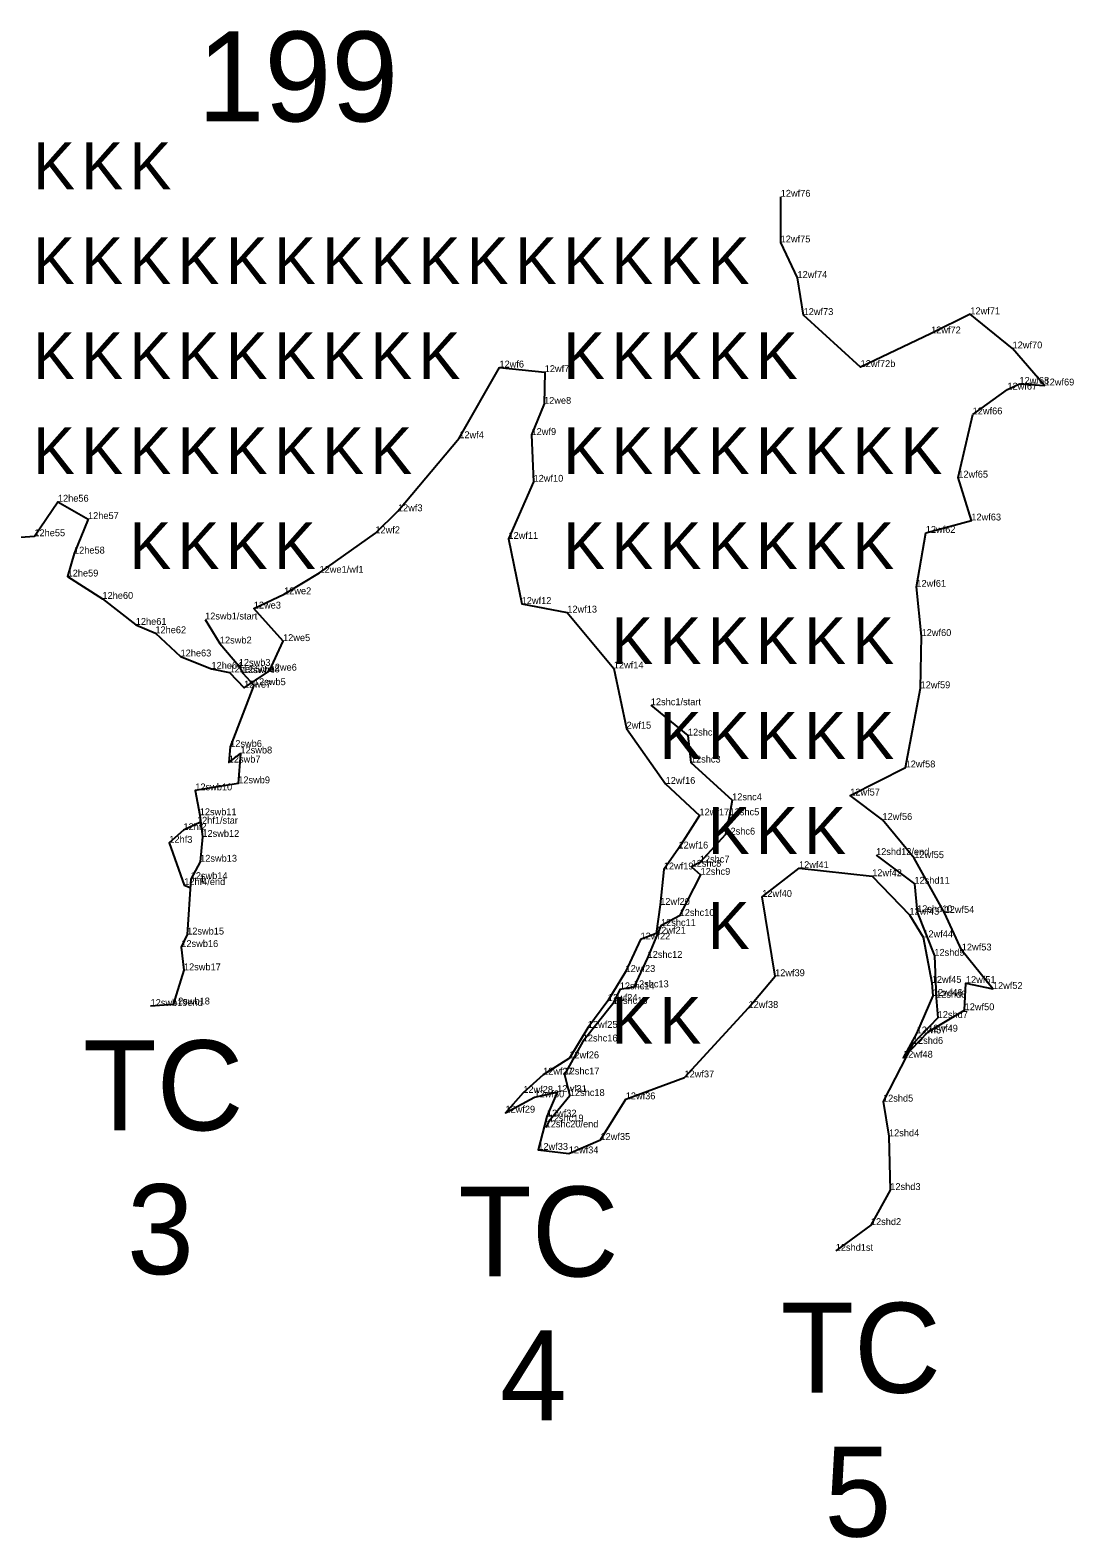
# Model space of a CAD drawing. Extents: x 2072529 to 2268812, y 436423 to 470008.
# Drawn here: x 2237884 to 2238642, y 451648 to 452743 of the extents above; entities that cross this region are included whole.
import ezdxf

# ---------------------------------------------------------------- set-up
doc = ezdxf.new("R2010")
doc.units = 0
for name, color, linetype in [('Old_Level_10', 7, 'Continuous'), ('Old_Level_20', 7, 'Continuous'), ('Old_Level_52', 7, 'Continuous'), ('Old_Level_55', 7, 'Continuous'), ('Old_Level_60', 7, 'Continuous'), ('Old_Level_62', 7, 'Continuous')]:
    doc.layers.add(name, color=color, linetype=linetype)

msp = doc.modelspace()

# ---------------------------------------------------------------- linework, layer by layer
at = {"layer": 'Old_Level_10'}
for points in [[(2238010.694, 452314.93), (2238021.436, 452297.482), (2238035.128, 452281.22), (2238038.188, 452275.967), (2238046.181, 452267.208), (2238028.905, 452222.291), (2238027.87, 452210.961), (2238036.35, 452217.58), (2238034.759, 452195.863), (2238003.583, 452190.757), (2238006.802, 452172.686), (2238008.719, 452156.976), (2238007.099, 452138.905), (2238000.224, 452126.284), (2237997.67, 452086.001), (2237993.422, 452076.932), (2237995.326, 452060.005), (2237987.388, 452035.188), (2237971.089, 452034.064)], [(2238334.377, 452252.615), (2238361.329, 452230.577), (2238363.498, 452210.976), (2238393.449, 452183.574), (2238391.606, 452172.684), (2238388.577, 452158.621), (2238369.952, 452138.34), (2238363.996, 452135.238), (2238370.517, 452129.385), (2238355.316, 452099.515), (2238341.777, 452092.23), (2238332.039, 452069.053), (2238322.096, 452047.692), (2238311.831, 452046.169), (2238306.711, 452035.572), (2238284.949, 452008.295), (2238271.773, 451984.32), (2238275.587, 451968.691), (2238260.246, 451950.175), (2238258.026, 451945.854)], [(2238497.962, 452143.757), (2238525.811, 452122.899), (2238527.782, 452102.252), (2238540.299, 452070.547), (2238541.55, 452040.093), (2238542.723, 452025.354), (2238524.713, 452006.572), (2238503.009, 451964.61), (2238507.357, 451939.378), (2238508.314, 451900.321), (2238494.238, 451874.878), (2238468.676, 451856.183)]]:
    msp.add_lwpolyline(points, dxfattribs=at)
at = {"layer": 'Old_Level_20'}
for p, q in [((2238428.754, 452622.108), (2238428.754, 452622.108)), ((2238428.688, 452588.913), (2238428.688, 452588.913)), ((2238440.919, 452563.086), (2238440.919, 452563.086)), ((2238445.35, 452536.145), (2238445.35, 452536.145)), ((2238566.421, 452536.684), (2238566.421, 452536.684)), ((2238537.913, 452522.786), (2238537.913, 452522.786)), ((2238597.097, 452511.893), (2238597.097, 452511.893)), ((2238224.44, 452498.01), (2238224.44, 452498.01)), ((2238257.347, 452494.702), (2238257.347, 452494.702)), ((2238486.692, 452498.346), (2238486.692, 452498.346)), ((2238593.365, 452481.95), (2238593.365, 452481.95)), ((2238602.128, 452486.166), (2238602.128, 452486.166)), ((2238620.342, 452484.972), (2238620.342, 452484.972)), ((2238256.845, 452471.636), (2238256.845, 452471.636)), ((2238568.126, 452463.954), (2238568.126, 452463.954)), ((2238195.306, 452446.648), (2238195.306, 452446.648)), ((2238247.757, 452448.981), (2238247.757, 452448.981)), ((2238249.24, 452415), (2238249.24, 452415)), ((2238557.699, 452417.986), (2238557.699, 452417.986)), ((2237903.805, 452400.503), (2237903.805, 452400.503)), ((2238150.75, 452393.563), (2238150.75, 452393.563)), ((2237925.67, 452387.897), (2237925.67, 452387.897)), ((2238567.164, 452386.879), (2238567.164, 452386.879)), ((2237886.707, 452375.423), (2237886.707, 452375.423)), ((2238134.357, 452377.566), (2238134.357, 452377.566)), ((2238230.999, 452373.486), (2238230.999, 452373.486)), ((2238534.042, 452377.877), (2238534.042, 452377.877)), ((2237915.502, 452362.798), (2237915.502, 452362.798)), ((2238093.818, 452348.854), (2238093.818, 452348.854)), ((2237910.844, 452346.147), (2237910.844, 452346.147)), ((2238527.222, 452338.653), (2238527.222, 452338.653)), ((2237936.142, 452329.916), (2237936.142, 452329.916)), ((2238068.042, 452333.209), (2238068.042, 452333.209)), ((2238240.609, 452326.185), (2238240.609, 452326.185)), ((2238010.694, 452314.93), (2238010.694, 452314.93)), ((2238046.054, 452322.857), (2238046.054, 452322.857)), ((2238273.736, 452319.926), (2238273.736, 452319.926)), ((2237960.357, 452311.031), (2237960.357, 452311.031)), ((2237974.582, 452304.915), (2237974.582, 452304.915)), ((2238021.436, 452297.482), (2238021.436, 452297.482)), ((2238067.306, 452299.224), (2238067.306, 452299.224)), ((2238531.044, 452302.91), (2238531.044, 452302.91)), ((2237992.865, 452288.065), (2237992.865, 452288.065)), ((2238035.128, 452281.22), (2238035.128, 452281.22)), ((2238015.323, 452279.08), (2238015.323, 452279.08)), ((2238028.454, 452276.468), (2238028.454, 452276.468)), ((2238038.188, 452275.967), (2238038.188, 452275.967)), ((2238057.58, 452277.721), (2238057.58, 452277.721)), ((2238307.495, 452279.357), (2238307.495, 452279.357)), ((2238038.976, 452265.371), (2238038.976, 452265.371)), ((2238046.181, 452267.208), (2238046.181, 452267.208)), ((2238530.302, 452264.957), (2238530.302, 452264.957)), ((2238334.377, 452252.615), (2238334.377, 452252.615)), ((2238316.78, 452235.619), (2238316.78, 452235.619)), ((2238361.329, 452230.577), (2238361.329, 452230.577)), ((2238028.905, 452222.291), (2238028.905, 452222.291)), ((2238036.35, 452217.58), (2238036.35, 452217.58)), ((2238027.87, 452210.961), (2238027.87, 452210.961)), ((2238363.498, 452210.976), (2238363.498, 452210.976)), ((2238519.451, 452207.413), (2238519.451, 452207.413)), ((2238034.759, 452195.863), (2238034.759, 452195.863)), ((2238345.147, 452195.473), (2238345.147, 452195.473)), ((2238003.583, 452190.757), (2238003.583, 452190.757)), ((2238393.449, 452183.574), (2238393.449, 452183.574)), ((2238479.177, 452186.975), (2238479.177, 452186.975)), ((2238006.802, 452172.686), (2238006.802, 452172.686)), ((2238369.696, 452172.554), (2238369.696, 452172.554)), ((2238391.606, 452172.684), (2238391.606, 452172.684)), ((2237994.958, 452161.838), (2237994.958, 452161.838)), ((2238004.774, 452166.517), (2238004.774, 452166.517)), ((2238502.65, 452169.283), (2238502.65, 452169.283)), ((2237984.711, 452152.648), (2237984.711, 452152.648)), ((2238008.719, 452156.976), (2238008.719, 452156.976)), ((2238388.577, 452158.621), (2238388.577, 452158.621)), ((2238007.099, 452138.905), (2238007.099, 452138.905)), ((2238354.479, 452148.509), (2238354.479, 452148.509)), ((2238497.962, 452143.757), (2238497.962, 452143.757)), ((2238525.69, 452141.534), (2238525.69, 452141.534)), ((2238343.8, 452133.304), (2238343.8, 452133.304)), ((2238363.996, 452135.238), (2238363.996, 452135.238)), ((2238369.952, 452138.34), (2238369.952, 452138.34)), ((2238370.517, 452129.385), (2238370.517, 452129.385)), ((2238442.006, 452134.254), (2238442.006, 452134.254)), ((2238495.147, 452128.396), (2238495.147, 452128.396)), ((2237995.555, 452121.937), (2237995.555, 452121.937)), ((2238000.224, 452126.284), (2238000.224, 452126.284)), ((2238525.811, 452122.899), (2238525.811, 452122.899)), ((2238341.19, 452107.554), (2238341.19, 452107.554)), ((2238415.298, 452113.343), (2238415.298, 452113.343)), ((2238355.316, 452099.515), (2238355.316, 452099.515)), ((2238522.222, 452100.399), (2238522.222, 452100.399)), ((2238527.782, 452102.252), (2238527.782, 452102.252)), ((2238547.732, 452101.763), (2238547.732, 452101.763)), ((2237997.67, 452086.001), (2237997.67, 452086.001)), ((2238338.222, 452086.667), (2238338.222, 452086.667)), ((2238341.777, 452092.23), (2238341.777, 452092.23)), ((2237993.422, 452076.932), (2237993.422, 452076.932)), ((2238326.939, 452082.393), (2238326.939, 452082.393)), ((2238532.285, 452083.974), (2238532.285, 452083.974)), ((2238560.242, 452074.441), (2238560.242, 452074.441)), ((2238332.039, 452069.053), (2238332.039, 452069.053)), ((2238540.299, 452070.547), (2238540.299, 452070.547)), ((2237995.326, 452060.005), (2237995.326, 452060.005)), ((2238316.036, 452058.821), (2238316.036, 452058.821)), ((2238424.641, 452055.729), (2238424.641, 452055.729)), ((2238311.831, 452046.169), (2238311.831, 452046.169)), ((2238322.096, 452047.692), (2238322.096, 452047.692)), ((2238538.391, 452050.899), (2238538.391, 452050.899)), ((2238539.198, 452041.453), (2238539.198, 452041.453)), ((2238563.236, 452050.769), (2238563.236, 452050.769)), ((2238582.841, 452046.454), (2238582.841, 452046.454)), ((2237971.089, 452034.064), (2237971.089, 452034.064)), ((2237987.388, 452035.188), (2237987.388, 452035.188)), ((2238303.159, 452037.74), (2238303.159, 452037.74)), ((2238306.711, 452035.572), (2238306.711, 452035.572)), ((2238405.34, 452032.672), (2238405.34, 452032.672)), ((2238541.55, 452040.093), (2238541.55, 452040.093)), ((2238562.293, 452031.009), (2238562.293, 452031.009)), ((2238542.723, 452025.354), (2238542.723, 452025.354)), ((2238284.949, 452008.295), (2238284.949, 452008.295)), ((2238288.648, 452018.187), (2238288.648, 452018.187)), ((2238527.444, 452014.123), (2238527.444, 452014.123)), ((2238535.792, 452015.406), (2238535.792, 452015.406)), ((2238517.576, 451996.474), (2238517.576, 451996.474)), ((2238524.713, 452006.572), (2238524.713, 452006.572)), ((2238275.222, 451996.049), (2238275.222, 451996.049)), ((2238256.128, 451984.144), (2238256.128, 451984.144)), ((2238271.773, 451984.32), (2238271.773, 451984.32)), ((2238358.819, 451982.175), (2238358.819, 451982.175)), ((2238241.784, 451970.96), (2238241.784, 451970.96)), ((2238249.919, 451967.741), (2238249.919, 451967.741)), ((2238266.359, 451971.532), (2238266.359, 451971.532)), ((2238275.587, 451968.691), (2238275.587, 451968.691)), ((2238316.145, 451966.255), (2238316.145, 451966.255)), ((2238503.009, 451964.61), (2238503.009, 451964.61)), ((2238228.787, 451956.554), (2238228.787, 451956.554)), ((2238258.869, 451953.728), (2238258.869, 451953.728)), ((2238258.026, 451945.854), (2238258.026, 451945.854)), ((2238260.246, 451950.175), (2238260.246, 451950.175)), ((2238297.838, 451936.702), (2238297.838, 451936.702)), ((2238507.357, 451939.378), (2238507.357, 451939.378)), ((2238252.683, 451929.538), (2238252.683, 451929.538)), ((2238274.77, 451927.01), (2238274.77, 451927.01)), ((2238508.314, 451900.321), (2238508.314, 451900.321)), ((2238494.238, 451874.878), (2238494.238, 451874.878)), ((2238468.676, 451856.183), (2238468.676, 451856.183))]:
    msp.add_line(p, q, dxfattribs=at)
at = {"layer": 'Old_Level_52'}
for points in [[(2238568.126, 452463.954), (2238593.365, 452481.95), (2238602.128, 452486.166), (2238620.342, 452484.972), (2238597.097, 452511.893), (2238566.421, 452536.684), (2238537.913, 452522.786), (2238486.692, 452498.346), (2238445.35, 452536.145), (2238440.919, 452563.086), (2238428.688, 452588.913), (2238428.754, 452622.108)], [(2237853.078, 452372.986), (2237886.707, 452375.423), (2237903.805, 452400.503), (2237925.67, 452387.897), (2237915.502, 452362.798), (2237910.844, 452346.147), (2237936.142, 452329.916), (2237960.357, 452311.031), (2237974.582, 452304.915), (2237992.865, 452288.065), (2238015.323, 452279.08), (2238028.454, 452276.468), (2238038.976, 452265.371), (2238057.58, 452277.721), (2238067.306, 452299.224), (2238046.054, 452322.857), (2238068.042, 452333.209), (2238093.818, 452348.854), (2238134.357, 452377.566), (2238150.75, 452393.563), (2238195.306, 452446.648), (2238224.44, 452498.01), (2238257.347, 452494.702), (2238256.845, 452471.636), (2238247.757, 452448.981), (2238249.24, 452415), (2238230.999, 452373.486), (2238240.609, 452326.185), (2238273.736, 452319.926), (2238307.495, 452279.357), (2238316.78, 452235.619), (2238345.147, 452195.473), (2238369.696, 452172.554), (2238354.479, 452148.509), (2238343.8, 452133.304), (2238341.19, 452107.554), (2238338.222, 452086.667), (2238326.939, 452082.393), (2238316.036, 452058.821), (2238303.159, 452037.74), (2238288.648, 452018.187), (2238275.222, 451996.049), (2238256.128, 451984.144), (2238241.784, 451970.96), (2238228.787, 451956.554), (2238249.919, 451967.741), (2238266.359, 451971.532), (2238258.869, 451953.728), (2238252.683, 451929.538), (2238274.77, 451927.01), (2238297.838, 451936.702), (2238316.145, 451966.255), (2238358.819, 451982.175), (2238405.34, 452032.672), (2238424.641, 452055.729), (2238415.298, 452113.343), (2238442.006, 452134.254), (2238495.147, 452128.396), (2238522.222, 452100.399), (2238532.285, 452083.974), (2238538.391, 452050.899), (2238539.198, 452041.453), (2238527.444, 452014.123), (2238517.576, 451996.474), (2238535.792, 452015.406), (2238562.293, 452031.009), (2238563.236, 452050.769), (2238582.841, 452046.454), (2238560.242, 452074.441), (2238547.732, 452101.763), (2238525.69, 452141.534), (2238502.65, 452169.283), (2238479.177, 452186.975), (2238519.451, 452207.413), (2238530.302, 452264.957), (2238531.044, 452302.91), (2238527.222, 452338.653), (2238534.042, 452377.877), (2238567.164, 452386.879), (2238557.699, 452417.986), (2238568.126, 452463.954)], [(2238007.402, 452167.769), (2237994.958, 452161.838), (2237984.711, 452152.648), (2237995.555, 452121.937), (2237999.833, 452120.117)]]:
    msp.add_lwpolyline(points, dxfattribs=at)

# ---------------------------------------------------------------- texts
at = {"layer": 'Old_Level_55'}
for p in [(2237885.782, 452627.593), (2237920.782, 452627.593), (2237955.782, 452627.593), (2237885.782, 452558.593), (2237920.782, 452558.593), (2237955.782, 452558.593), (2237990.782, 452558.593), (2238025.782, 452558.593), (2238060.782, 452558.593), (2238095.782, 452558.593), (2238130.782, 452558.593), (2238165.782, 452558.593), (2238200.782, 452558.593), (2238235.782, 452558.593), (2238270.782, 452558.593), (2238305.782, 452558.593), (2238340.782, 452558.593), (2238375.782, 452558.593), (2237885.782, 452489.593), (2237920.782, 452489.593), (2237955.782, 452489.593), (2237990.782, 452489.593), (2238025.782, 452489.593), (2238060.782, 452489.593), (2238095.782, 452489.593), (2238130.782, 452489.593), (2238165.782, 452489.593), (2238270.782, 452489.593), (2238305.782, 452489.593), (2238340.782, 452489.593), (2238375.782, 452489.593), (2238410.782, 452489.593), (2237885.782, 452420.593), (2237920.782, 452420.593), (2237955.782, 452420.593), (2237990.782, 452420.593), (2238025.782, 452420.593), (2238060.782, 452420.593), (2238095.782, 452420.593), (2238130.782, 452420.593), (2238270.782, 452420.593), (2238305.782, 452420.593), (2238340.782, 452420.593), (2238375.782, 452420.593), (2238410.782, 452420.593), (2238445.782, 452420.593), (2238480.782, 452420.593), (2238515.782, 452420.593), (2237955.782, 452351.593), (2237990.782, 452351.593), (2238025.782, 452351.593), (2238060.782, 452351.593), (2238270.782, 452351.593), (2238305.782, 452351.593), (2238340.782, 452351.593), (2238375.782, 452351.593), (2238410.782, 452351.593), (2238445.782, 452351.593), (2238480.782, 452351.593), (2238305.782, 452282.593), (2238340.782, 452282.593), (2238375.782, 452282.593), (2238410.782, 452282.593), (2238445.782, 452282.593), (2238480.782, 452282.593), (2238340.782, 452213.593), (2238375.782, 452213.593), (2238410.782, 452213.593), (2238445.782, 452213.593), (2238480.782, 452213.593), (2238375.782, 452144.593), (2238410.782, 452144.593), (2238445.782, 452144.593), (2238375.782, 452075.593), (2238305.782, 452006.593), (2238340.782, 452006.593)]:
    msp.add_text('K', height=34, dxfattribs=at).set_placement(p)
at = {"layer": 'Old_Level_60'}
for s, p in [('12wf76', (2238428.754, 452622.108)), ('12wf75', (2238428.688, 452588.913)), ('12wf74', (2238440.919, 452563.086)), ('12wf73', (2238445.35, 452536.145)), ('12wf71', (2238566.421, 452536.684)), ('12wf72', (2238537.913, 452522.786)), ('12wf70', (2238597.097, 452511.893)), ('12wf6', (2238224.44, 452498.01)), ('12wf72b', (2238486.692, 452498.346)), ('12wf7', (2238257.347, 452494.702)), ('12wf68', (2238602.128, 452486.166)), ('12wf69', (2238620.342, 452484.972)), ('12wf67', (2238593.365, 452481.95)), ('12we8', (2238256.845, 452471.636)), ('12wf66', (2238568.126, 452463.954)), ('12wf4', (2238195.306, 452446.648)), ('12wf9', (2238247.757, 452448.981)), ('12wf10', (2238249.24, 452415)), ('12wf65', (2238557.699, 452417.986)), ('12he56', (2237903.805, 452400.503)), ('12he57', (2237925.67, 452387.897)), ('12wf3', (2238150.75, 452393.563)), ('12wf63', (2238567.164, 452386.879)), ('12he55', (2237886.707, 452375.423)), ('12wf2', (2238134.357, 452377.566)), ('12wf62', (2238534.042, 452377.877)), ('12wf11', (2238230.999, 452373.486)), ('12he58', (2237915.502, 452362.798)), ('12he59', (2237910.844, 452346.147)), ('12we1/wf1', (2238093.818, 452348.854)), ('12we2', (2238068.042, 452333.209)), ('12wf61', (2238527.222, 452338.653)), ('12he60', (2237936.142, 452329.916)), ('12we3', (2238046.054, 452322.857)), ('12wf12', (2238240.609, 452326.185)), ('12wf13', (2238273.736, 452319.926)), ('12he61', (2237960.357, 452311.031)), ('12swb1/start', (2238010.694, 452314.93)), ('12he62', (2237974.582, 452304.915)), ('12we5', (2238067.306, 452299.224)), ('12wf60', (2238531.044, 452302.91)), ('12he63', (2237992.865, 452288.065)), ('12swb2', (2238021.436, 452297.482)), ('12he64', (2238015.323, 452279.08)), ('12he65/we8', (2238028.454, 452276.468)), ('12swb3', (2238035.128, 452281.22)), ('12swb4', (2238038.188, 452275.967)), ('12we6', (2238057.58, 452277.721)), ('12wf14', (2238307.495, 452279.357)), ('12we7', (2238038.976, 452265.371)), ('12swb5', (2238046.181, 452267.208)), ('12wf59', (2238530.302, 452264.957)), ('12shc1/start', (2238334.377, 452252.615)), ('2wf15', (2238316.78, 452235.619)), ('12swb6', (2238028.905, 452222.291)), ('12shc2', (2238361.329, 452230.577)), ('12swb7', (2238027.87, 452210.961)), ('12swb8', (2238036.35, 452217.58)), ('12shc3', (2238363.498, 452210.976)), ('12wf58', (2238519.451, 452207.413)), ('12swb10', (2238003.583, 452190.757)), ('12swb9', (2238034.759, 452195.863)), ('12wf16', (2238345.147, 452195.473)), ('12snc4', (2238393.449, 452183.574)), ('12wf57', (2238479.177, 452186.975)), ('12hf1/star', (2238004.774, 452166.517)), ('12swb11', (2238006.802, 452172.686)), ('12wf17', (2238369.696, 452172.554)), ('12shc5', (2238391.606, 452172.684)), ('12wf56', (2238502.65, 452169.283)), ('12hf2', (2237994.958, 452161.838)), ('12swb12', (2238008.719, 452156.976)), ('12shc6', (2238388.577, 452158.621)), ('12hf3', (2237984.711, 452152.648)), ('12wf16', (2238354.479, 452148.509)), ('12swb13', (2238007.099, 452138.905)), ('12shc8', (2238363.996, 452135.238)), ('12shc7', (2238369.952, 452138.34)), ('12wf41', (2238442.006, 452134.254)), ('12shd12/end', (2238497.962, 452143.757)), ('12wf55', (2238525.69, 452141.534)), ('12swb14', (2238000.224, 452126.284)), ('1', (2238006.802, 452124.004)), ('12wf19', (2238343.8, 452133.304)), ('12shc9', (2238370.517, 452129.385)), ('12wf42', (2238495.147, 452128.396)), ('12shd11', (2238525.811, 452122.899)), ('12hf4/end', (2237995.555, 452121.937)), ('12wf40', (2238415.298, 452113.343)), ('12wf20', (2238341.19, 452107.554)), ('12shd10', (2238527.782, 452102.252)), ('12wf54', (2238547.732, 452101.763)), ('12shc11', (2238341.777, 452092.23)), ('12shc10', (2238355.316, 452099.515)), ('12wf43', (2238522.222, 452100.399)), ('12swb15', (2237997.67, 452086.001)), ('12wf22', (2238326.939, 452082.393)), ('12wf21', (2238338.222, 452086.667)), ('12wf44', (2238532.285, 452083.974)), ('12swb16', (2237993.422, 452076.932)), ('12shc12', (2238332.039, 452069.053)), ('12shd9', (2238540.299, 452070.547)), ('12wf53', (2238560.242, 452074.441)), ('12swb17', (2237995.326, 452060.005)), ('12wf23', (2238316.036, 452058.821)), ('12shc14', (2238311.831, 452046.169)), ('12shc13', (2238322.096, 452047.692)), ('12wf39', (2238424.641, 452055.729)), ('12wf45', (2238538.391, 452050.899)), ('12wf51', (2238563.236, 452050.769)), ('12wf52', (2238582.841, 452046.454)), ('12swb18', (2237987.388, 452035.188)), ('12wf24', (2238303.159, 452037.74)), ('12shc15', (2238306.711, 452035.572)), ('12wf46', (2238539.198, 452041.453)), ('12shd8', (2238541.55, 452040.093)), ('12swb19end', (2237971.089, 452034.064)), ('12wf38', (2238405.34, 452032.672)), ('12shd7', (2238542.723, 452025.354)), ('12wf50', (2238562.293, 452031.009)), ('12wf25', (2238288.648, 452018.187)), ('12wf57', (2238527.444, 452014.123)), ('12wf49', (2238535.792, 452015.406)), ('12shc16', (2238284.949, 452008.295)), ('12shd6', (2238524.713, 452006.572)), ('12wf26', (2238275.222, 451996.049)), ('12wf48', (2238517.576, 451996.474)), ('12wf27', (2238256.128, 451984.144)), ('12shc17', (2238271.773, 451984.32)), ('12wf37', (2238358.819, 451982.175)), ('12wf28', (2238241.784, 451970.96)), ('12wf31', (2238266.359, 451971.532)), ('12wf30', (2238249.919, 451967.741)), ('12shc18', (2238275.587, 451968.691)), ('12wf36', (2238316.145, 451966.255)), ('12shd5', (2238503.009, 451964.61)), ('12wf29', (2238228.787, 451956.554)), ('12wf32', (2238258.869, 451953.728)), ('12shc19', (2238260.246, 451950.175)), ('12shc20/end', (2238258.026, 451945.854)), ('12wf35', (2238297.838, 451936.702)), ('12shd4', (2238507.357, 451939.378)), ('12wf33', (2238252.683, 451929.538)), ('12wf34', (2238274.77, 451927.01)), ('12shd3', (2238508.314, 451900.321)), ('12shd2', (2238494.238, 451874.878)), ('12shd1st', (2238468.676, 451856.183))]:
    msp.add_text(s, height=5, dxfattribs=at).set_placement(p)
at = {"layer": 'Old_Level_62'}
for s, p in [('199', (2238005.183, 452676.836)), ('TC', (2237922.094, 451943.754)), ('3', (2237953.977, 451839.21)), ('TC', (2238194.544, 451837.55)), ('TC', (2238428.564, 451753.085)), ('4', (2238224.884, 451733.006)), ('5', (2238460.447, 451648.541))]:
    msp.add_text(s, height=65.34, dxfattribs=at).set_placement(p)

doc.saveas('drawing.dxf')
